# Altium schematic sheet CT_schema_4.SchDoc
size 573 x 363 mm
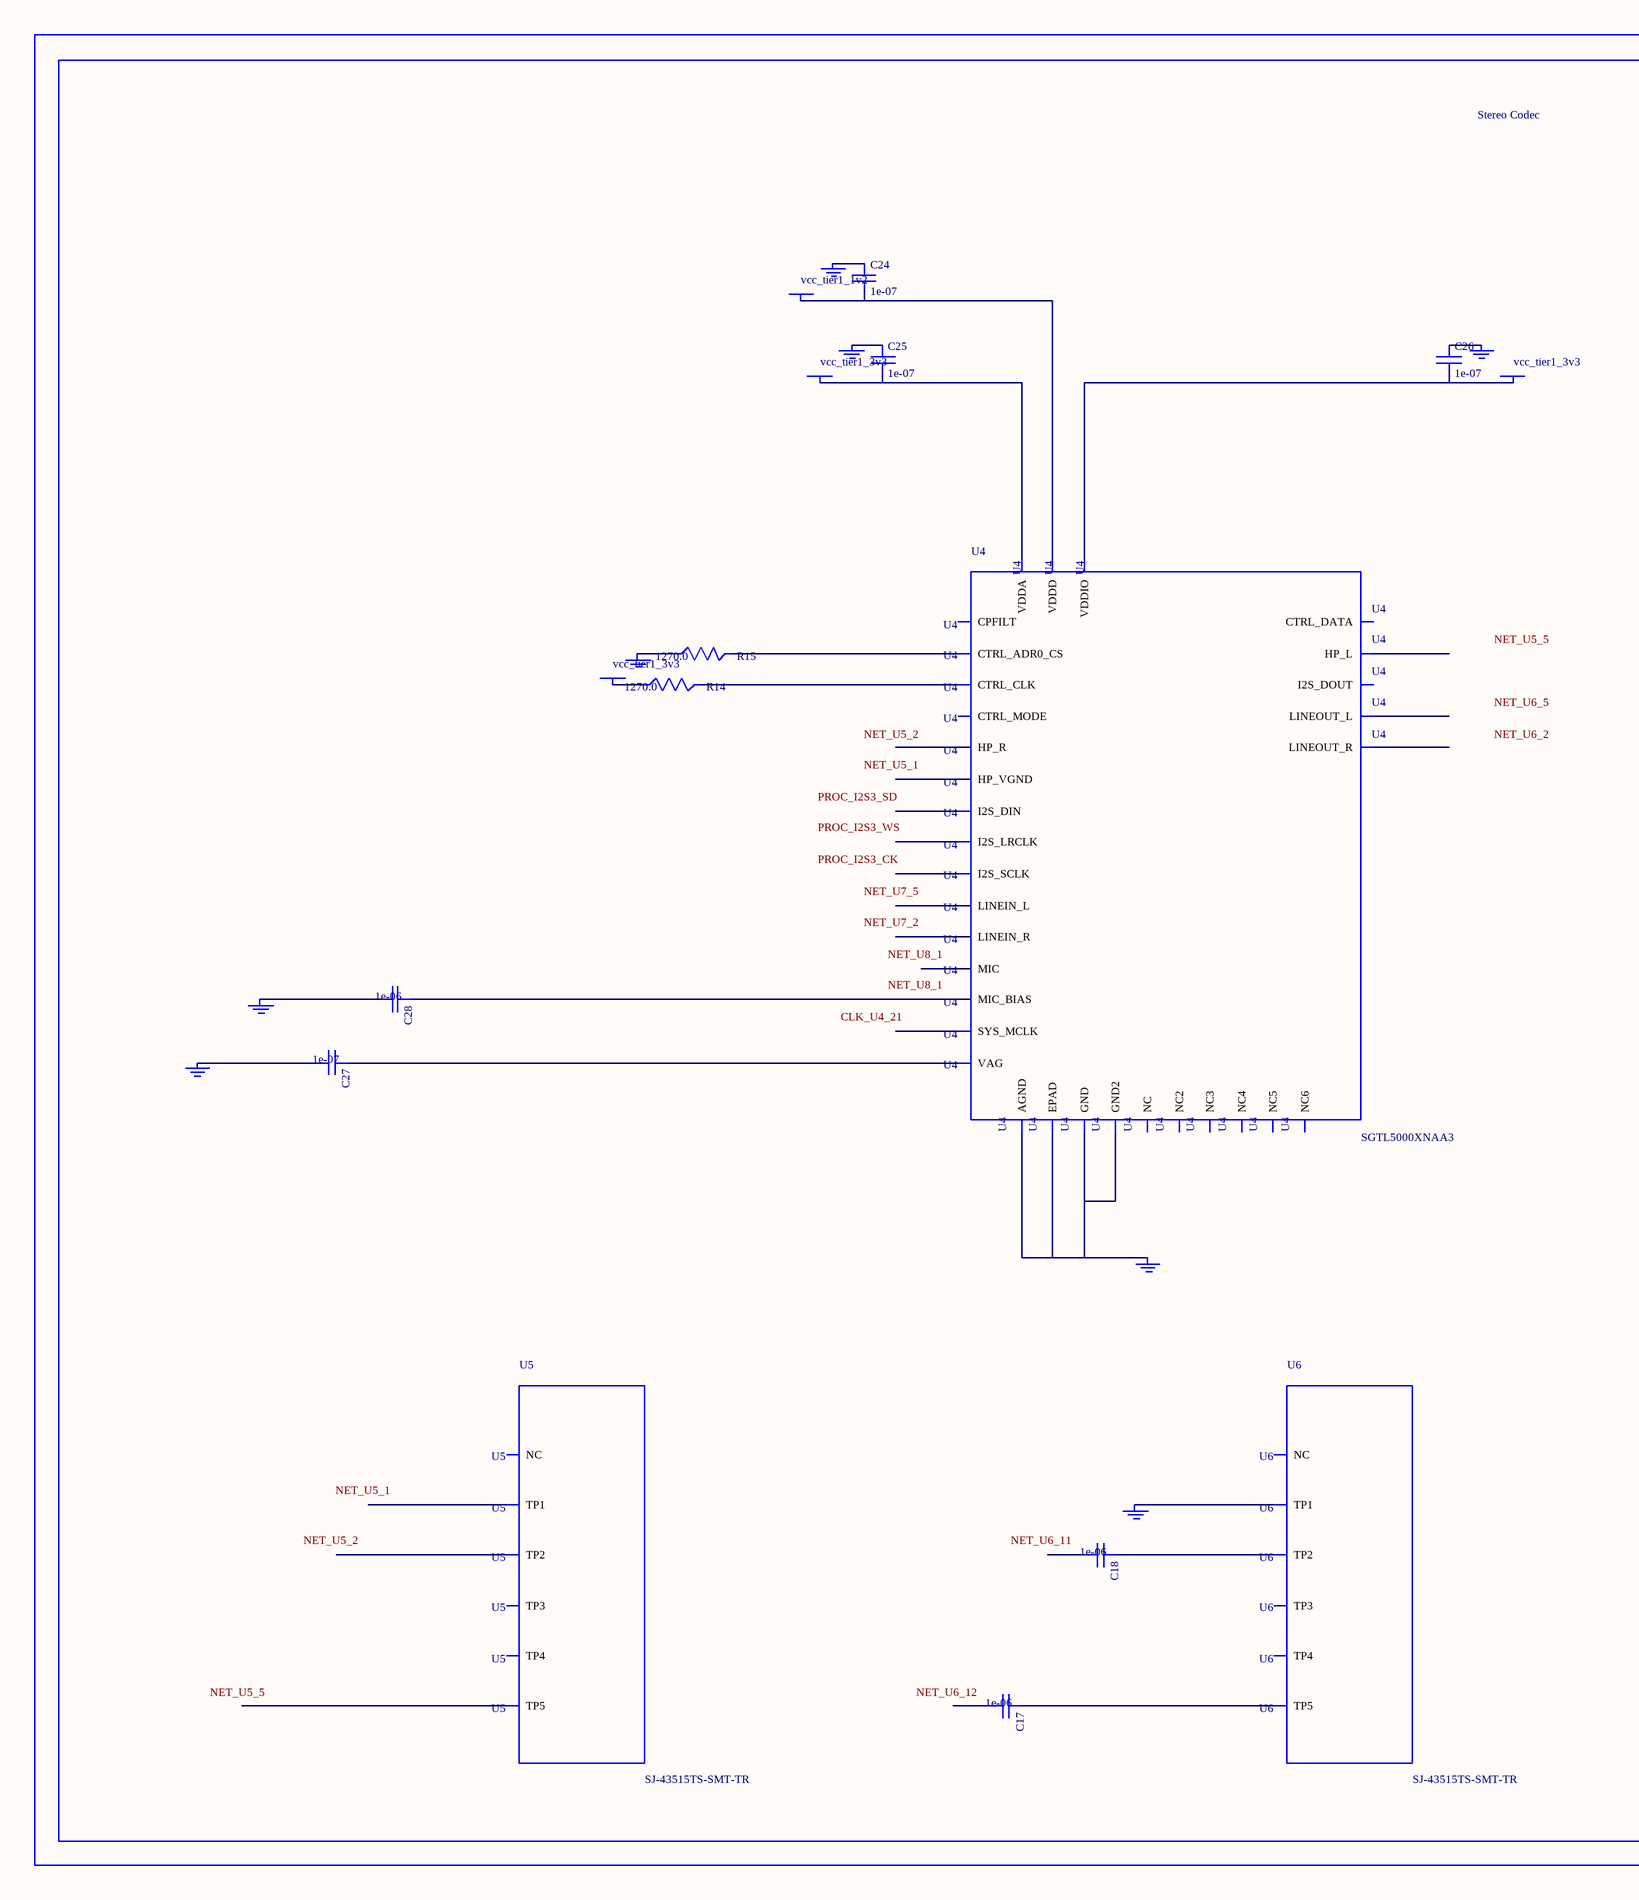
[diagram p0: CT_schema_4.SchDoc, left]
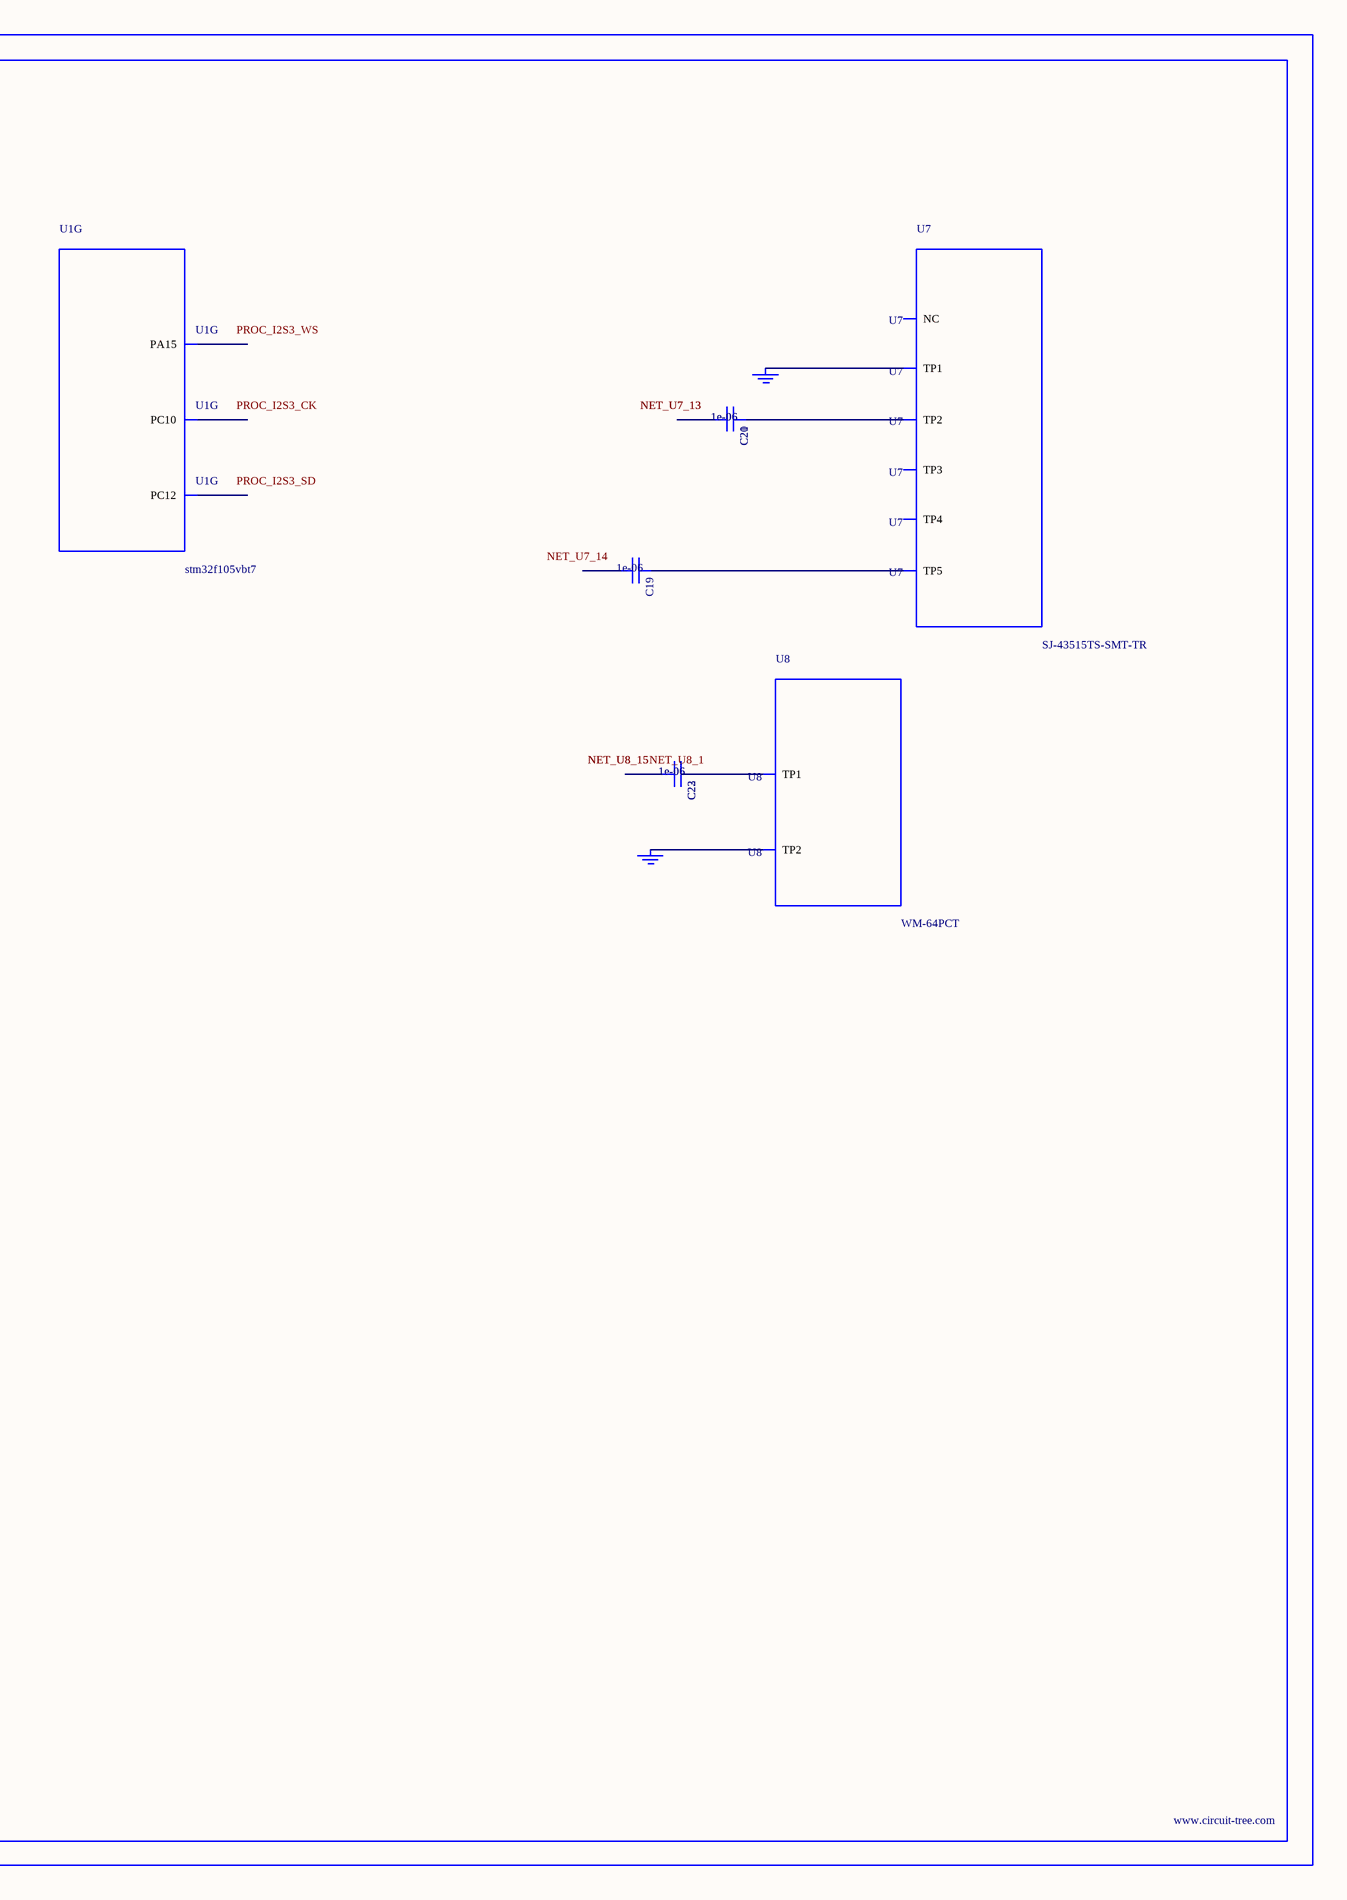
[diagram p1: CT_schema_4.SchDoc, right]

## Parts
BORDER3  (no value)
C17  1e-06  [C0603]
C18  1e-06  [C0603]
C19  1e-06  [C0603]
C20  1e-06  [C0603]
C21  1e-06  [C0603]
C22  1e-06  [C0603]
C23  1e-06  [C0603]
C24  1e-07  [C0402]
C25  1e-07  [C0402]
C26  1e-07  [C0402]
C27  1e-07  [C0402]
C28  1e-06  [C0603]
GND_INSTANCE_3_0  (no value)
GND_INSTANCE_3_1  (no value)
GND_INSTANCE_3_2  (no value)
GND_INSTANCE_3_3  (no value)
GND_INSTANCE_3_4  (no value)
GND_INSTANCE_3_5  (no value)
GND_INSTANCE_3_6  (no value)
GND_INSTANCE_3_7  (no value)
GND_INSTANCE_3_8  (no value)
GND_INSTANCE_3_9  (no value)
GND_INSTANCE_3_10  (no value)
POWER_INSTANCE_3_0  vcc_tier1_3v3
POWER_INSTANCE_3_1  vcc_tier1_3v3
POWER_INSTANCE_3_2  vcc_tier1_3v3
POWER_INSTANCE_3_3  vcc_tier1_1v2
R14  1270.0  [R0603]
R15  1270.0  [R0603]
U1  stm32f105vbt7  [LQFP100]  (part G of 10)
U4  SGTL5000XNAA3  [QFN-32]
U5  SJ-43515TS-SMT-TR  [SJ-43515TS-SMT-TR]
U6  SJ-43515TS-SMT-TR  [SJ-43515TS-SMT-TR]
U7  SJ-43515TS-SMT-TR  [SJ-43515TS-SMT-TR]
U8  WM-64PCT  [WM-64PC]

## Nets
NetC17_1: C17.1 U6.5(TP5)
NetC18_1: C18.1 U6.2(TP2)
NetC19_1: C19.1 U7.5(TP5)
NetC20_1: C20.1 C21.1 U7.2(TP2)
NetC20_2: C20.2 C21.2
NetC22_1: C22.1 C23.1 U8.1(TP1)
NetC22_2: C22.2 C23.2
NetC24_1: C24.1 GND_INSTANCE_3_5.0(GND)
NetC24_2: C24.2 POWER_INSTANCE_3_3.0(PWR) U4.30(VDDD)
NetC25_1: C25.1 GND_INSTANCE_3_1.0(GND)
NetC25_2: C25.2 POWER_INSTANCE_3_0.0(PWR) U4.5(VDDA)
NetC26_1: C26.1 GND_INSTANCE_3_4.0(GND)
NetC26_2: C26.2 POWER_INSTANCE_3_1.0(PWR) U4.20(VDDIO)
NetC27_1: C27.1 U4.10(VAG)
NetC27_2: C27.2 GND_INSTANCE_3_2.0(GND)
NetC28_1: C28.1 U4.16(MIC_BIAS)
NetC28_2: C28.2 GND_INSTANCE_3_3.0(GND)
NetGND_INSTANCE_3_0_0: GND_INSTANCE_3_0.0(GND) U4.1(GND) U4.3(GND2) U4.7(AGND) U4.EXP(EPAD)
NetGND_INSTANCE_3_6_0: GND_INSTANCE_3_6.0(GND) R15.1
NetGND_INSTANCE_3_7_0: GND_INSTANCE_3_7.0(GND) U6.1(TP1)
NetGND_INSTANCE_3_8_0: GND_INSTANCE_3_8.0(GND) GND_INSTANCE_3_9.0(GND) U7.1(TP1)
NetGND_INSTANCE_3_10_0: GND_INSTANCE_3_10.0(GND) U8.2(TP2)
NetPOWER_INSTANCE_3_2_0: POWER_INSTANCE_3_2.0(PWR) R14.1
NetR14_2: R14.2 U4.29(CTRL_CLK)
NetR15_2: R15.2 U4.31(CTRL_ADR0_CS)

Not connected (* = marked no-connect by the designer): C17 2; C18 2; C19 2; U1 77(PA15) 78(PC10) 80(PC12); U4 2(HP_R) 4(HP_VGND) 6(HP_L) 8(NC) 9(NC2) 11(LINEOUT_R) 12(LINEOUT_L) 13(LINEIN_R) 14(LINEIN_L) 15(MIC) 17(NC3) 18(CPFILT) 19(NC4) 21(SYS_MCLK) 22(NC5) 23(I2S_LRCLK) 24(I2S_SCLK) 25(I2S_DOUT) 26(I2S_DIN) 27(CTRL_DATA) 28(NC6) 32(CTRL_MODE); U5 1(TP1) 2(TP2) 3(TP3) 4(TP4) 5(TP5) 6(NC); U6 3(TP3) 4(TP4) 6(NC); U7 3(TP3) 4(TP4) 6(NC)

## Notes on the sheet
- Labels drawn without touching a wire or pin: CLK_U4_21, NET_U5_1, NET_U5_2, NET_U5_5, NET_U6_2, NET_U6_5, NET_U6_11, NET_U6_12, NET_U7_2, NET_U7_5, NET_U7_14, NET_U8_1, PROC_I2S3_CK, PROC_I2S3_SD, PROC_I2S3_WS

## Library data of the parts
BORDER3 = BORDER_PAGE3
C17-C23 C28 = C0603C105K3RACTU
C24-C27 = C0402C104K3RACTU
GND_INSTANCE_3_0-GND_INSTANCE_3_10 = GND
POWER_INSTANCE_3_0-POWER_INSTANCE_3_3 = PWR
R14 R15 = RC0603FR-071K27L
